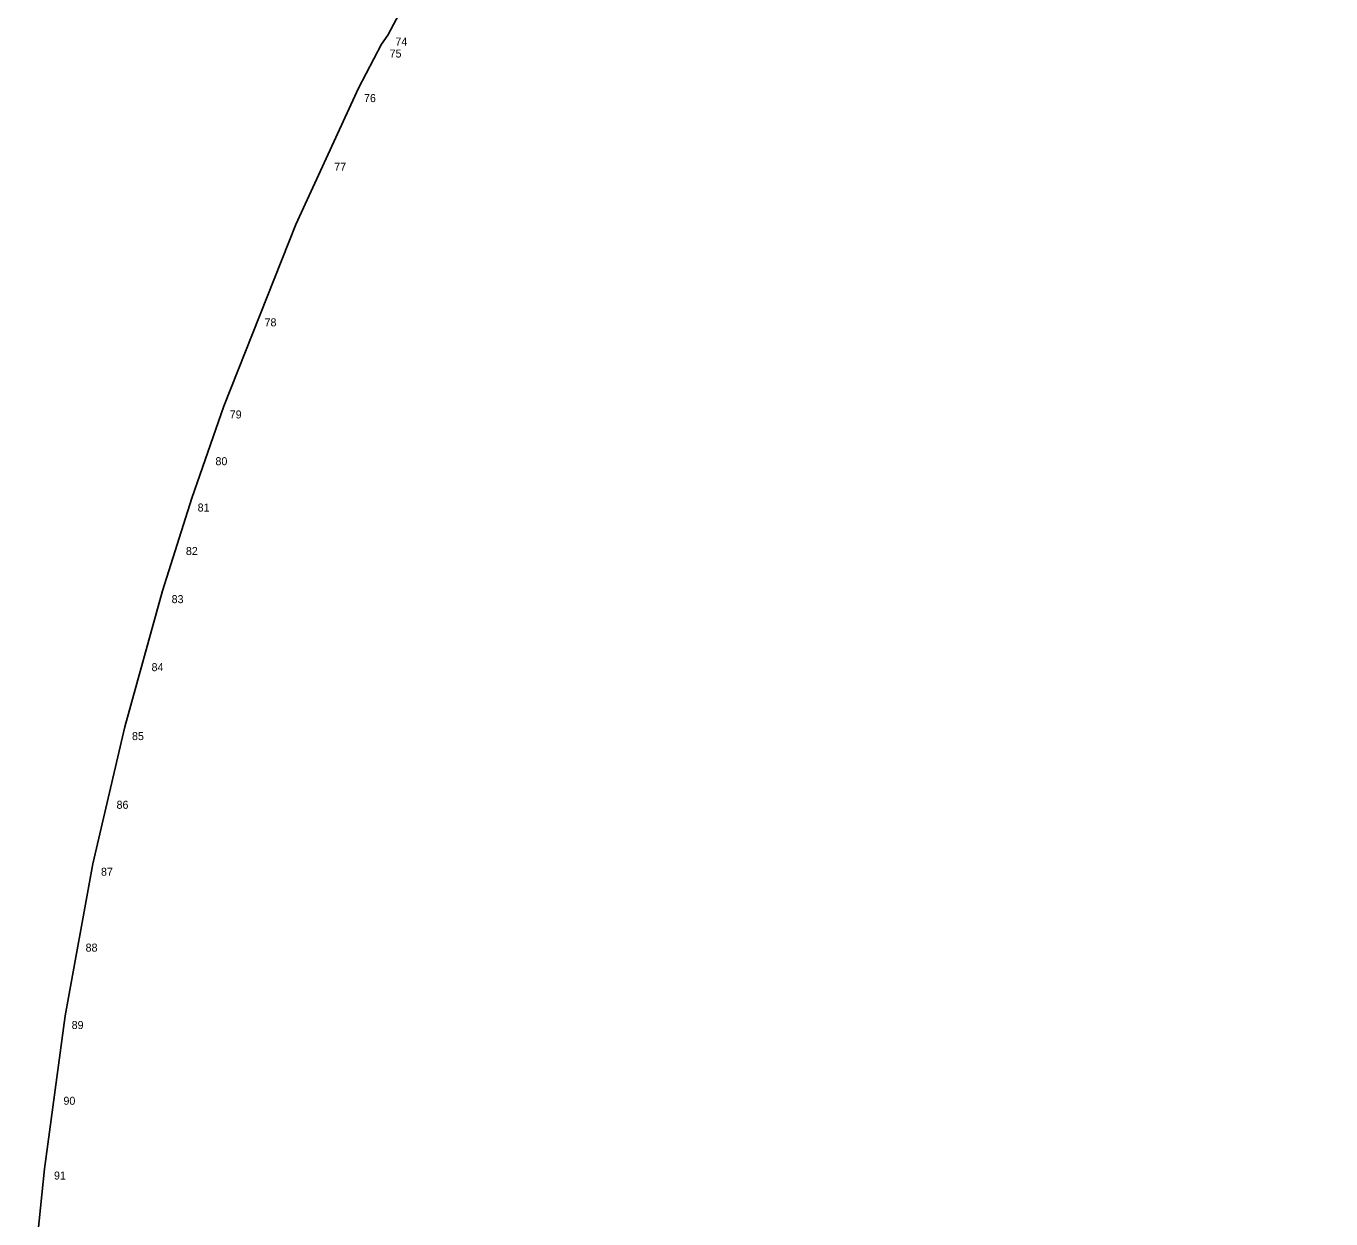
# Model space of a CAD drawing. Extents: x -743397 to -742769, y -1127804 to -1126284.
# Drawn here: x -743321.6 to -743125.9, y -1127423.3 to -1127244.4 of the extents above; entities that cross this region are included whole.
import ezdxf

# ---------------------------------------------------------------- set-up
doc = ezdxf.new("R2010")
doc.units = 0
for name, color, linetype in [('_Zabezpečovací zařízení_trasa', 7, 'Continuous'), ('křížky', 7, 'Continuous'), ('Vrstva 60', 7, 'Continuous')]:
    doc.layers.add(name, color=color, linetype=linetype)

# ---------------------------------------------------------------- blocks, each defined once
blk = doc.blocks.new('POINT_DISPLAY')
blk.add_line((0, 0), (0, 0))

msp = doc.modelspace()

# ---------------------------------------------------------------- linework, layer by layer
at = {"layer": '_Zabezpečovací zařízení_trasa'}
msp.add_lwpolyline([(-743125.94, -1127017.38), (-743152.6, -1127059.61), (-743175.02, -1127095.12), (-743199.16, -1127133.35), (-743215.97, -1127159.94), (-743232.82, -1127186.51), (-743247.46, -1127209.81), (-743254.52, -1127221.64), (-743261.3, -1127233.69), (-743264.16, -1127239.2), (-743264.86, -1127241.11), (-743267.34, -1127245.82), (-743268.29, -1127247.16), (-743271.71, -1127253.75), (-743281.12, -1127274.2), (-743291.92, -1127301.42), (-743296.72, -1127315.22), (-743301.12, -1127329.13), (-743306.79, -1127349.51), (-743311.54, -1127370.06), (-743315.69, -1127392.87), (-743318.79, -1127415.84), (-743321.57, -1127442.6)], dxfattribs=at)
at = {"layer": 'Vrstva 60'}
for p, q in [((-743267.34, -1127245.82), (-743267.34, -1127245.82)), ((-743268.29, -1127247.16), (-743268.29, -1127247.16)), ((-743271.71, -1127253.75), (-743271.71, -1127253.75)), ((-743276.42, -1127263.97), (-743276.42, -1127263.97)), ((-743286.52, -1127287.81), (-743286.52, -1127287.81)), ((-743291.92, -1127301.42), (-743291.92, -1127301.42)), ((-743294.32, -1127308.32), (-743294.32, -1127308.32)), ((-743296.72, -1127315.22), (-743296.72, -1127315.22)), ((-743298.92, -1127322.18), (-743298.92, -1127322.18)), ((-743301.12, -1127329.13), (-743301.12, -1127329.13)), ((-743303.95, -1127339.32), (-743303.95, -1127339.32)), ((-743306.79, -1127349.51), (-743306.79, -1127349.51)), ((-743309.16, -1127359.78), (-743309.16, -1127359.78)), ((-743311.54, -1127370.06), (-743311.54, -1127370.06)), ((-743313.61, -1127381.46), (-743313.61, -1127381.46)), ((-743315.69, -1127392.87), (-743315.69, -1127392.87)), ((-743317.24, -1127404.35), (-743317.24, -1127404.35)), ((-743318.79, -1127415.84), (-743318.79, -1127415.84))]:
    msp.add_line(p, q, dxfattribs=at)

# ---------------------------------------------------------------- block references
at = {"layer": 'křížky', "xscale": 10, "yscale": 10, "rotation": 61.14491455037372}
for p in [(-743267.34, -1127245.82), (-743268.29, -1127247.16), (-743271.71, -1127253.75), (-743276.42, -1127263.97), (-743286.52, -1127287.81), (-743291.92, -1127301.42), (-743294.32, -1127308.32), (-743296.72, -1127315.22), (-743298.92, -1127322.18), (-743301.12, -1127329.13), (-743303.95, -1127339.32), (-743306.79, -1127349.51), (-743309.16, -1127359.78), (-743311.54, -1127370.06), (-743313.61, -1127381.46), (-743315.69, -1127392.87), (-743317.24, -1127404.35), (-743318.79, -1127415.84)]:
    msp.add_blockref('POINT_DISPLAY', p, dxfattribs=at)

# ---------------------------------------------------------------- texts
at = {"layer": 'Vrstva 60'}
for s, p in [('74', (-743266.2, -1127247.36)), ('75', (-743267.07, -1127249.15)), ('76', (-743270.91, -1127255.84)), ('77', (-743275.37, -1127266.13)), ('78', (-743285.82, -1127289.47)), ('79', (-743291.04, -1127303.28)), ('80', (-743293.18, -1127310.29)), ('81', (-743295.85, -1127317.24)), ('82', (-743297.61, -1127323.76)), ('83', (-743299.75, -1127330.98)), ('84', (-743302.76, -1127341.18)), ('85', (-743305.69, -1127351.52)), ('86', (-743308.01, -1127361.82)), ('87', (-743310.34, -1127371.86)), ('88', (-743312.65, -1127383.24)), ('89', (-743314.74, -1127394.85)), ('90', (-743315.97, -1127406.21)), ('91', (-743317.39, -1127417.42))]:
    msp.add_text(s, height=1.2, dxfattribs=at).set_placement(p)

doc.saveas('drawing.dxf')
